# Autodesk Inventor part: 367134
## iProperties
Created: 2006-08
Part Number: 367134
Material: 8.8 vz
Description: Zylinderschraube
Vendor: Autodesk Inc.
Document SubType Name: Modeling
Standard: DIN 912
Designer: I.Baliuc
Standards Organization: DIN
Language: de-DE
Size Designation: M12 x 50
Categories: <MemberInstance Version="R10.0.0"><Categories><Category DisplayName="Schrauben" InternalName="e4da775c-781d-43d5-af7c-5136215cf5a6" Mnemonic="FSTN"><Category Di
Density: 7.85 g/cm^3
Mass: 63.1009 g
Surface Area: 32.4892 cm^2
Volume: 8.03833 cm^3
Abmessung: M12 x 50
Author: T.Messerschmitt
Comments: DIN 912 - M12 x 50
Revision Number: 367134
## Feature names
1. Körper [Revolution]
2. Loch [Extrusion]
3. Rundung1 [Fillet]
4. Fase1 [Chamfer]
